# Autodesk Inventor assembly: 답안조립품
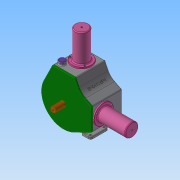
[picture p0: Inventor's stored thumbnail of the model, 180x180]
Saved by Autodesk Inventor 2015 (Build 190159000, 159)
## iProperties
Created: 2022-01
Part Number: 답안조립품
Document SubType Name: Assembly
Designer: user
Author: user
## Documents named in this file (13)
- C:\Users\user\Desktop\620117V1009\답안조립품.iam
- C:\Users\user\Desktop\620117V1009\너트 M3.ipt
- C:\Users\user\Desktop\620117V1009\베어링 20 x 37 x 9.ipt
- C:\Users\user\Desktop\620117V1009\본체.ipt
- C:\Users\user\Desktop\620117V1009\볼트 M3 x 12.ipt
- C:\Users\user\Desktop\620117V1009\실린더.ipt
- C:\Users\user\Desktop\620117V1009\앞커버.ipt
- C:\Users\user\Desktop\620117V1009\축.ipt
- C:\Users\user\Desktop\620117V1009\측정게이지.ipt
- C:\Users\user\Desktop\620117V1009\커넥팅로드 캡.ipt
- C:\Users\user\Desktop\620117V1009\커넥팅로드.ipt
- C:\Users\user\Desktop\620117V1009\피스톤 핀.ipt
- C:\Users\user\Desktop\620117V1009\피스톤.ipt
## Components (4 placed, 2 different names)
1. 피스톤 핀:1
2. 피스톤:1
3. 피스톤:2
4. 피스톤 핀:2
